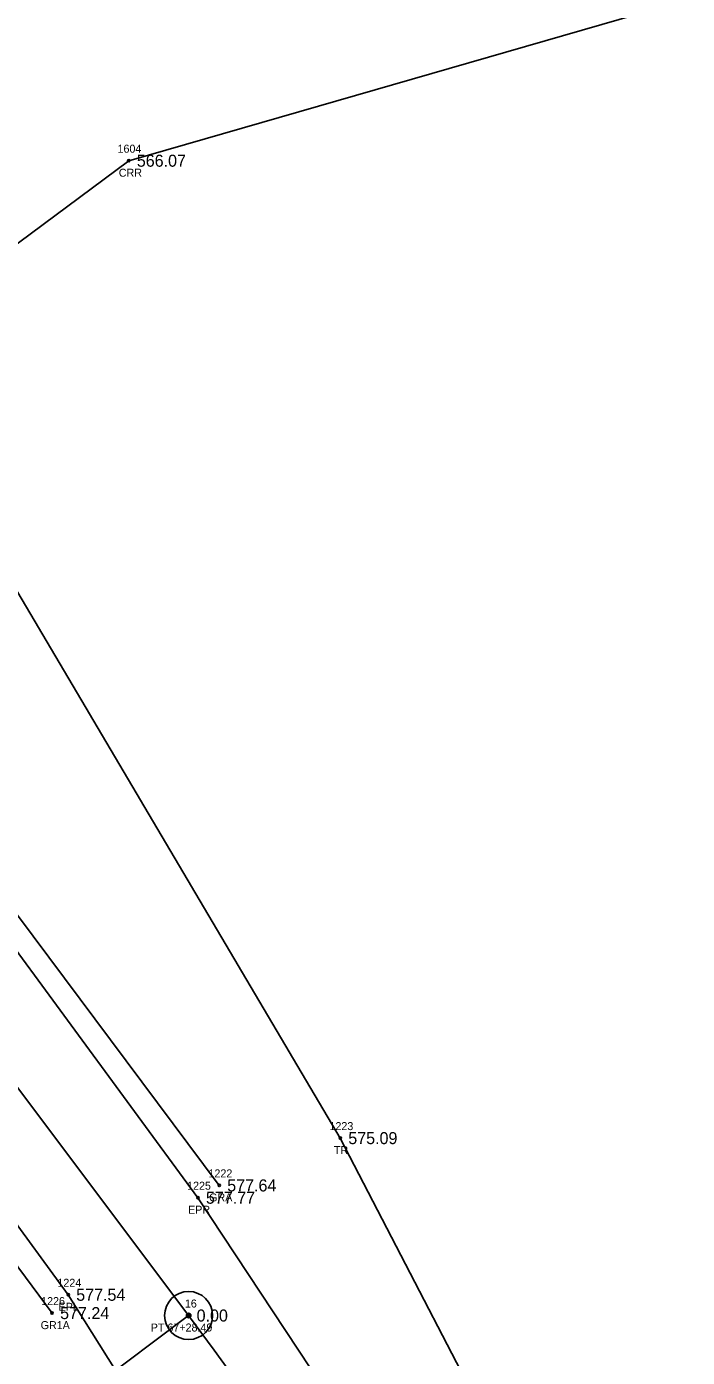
# Model space of a CAD drawing. Extents: x 1694813 to 1696862, y 1086485 to 1091027.
# Drawn here: x 1695951.1 to 1696033.6, y 1088933.9 to 1089100.2 of the extents above; entities that cross this region are included whole.
import ezdxf

# ---------------------------------------------------------------- set-up
doc = ezdxf.new("R2010")
doc.units = 0
for name, color, linetype in [('RD_EX_GuardRail', 7, 'Continuous'), ('RD_EX_GuardRail_txCode', 7, 'Continuous'), ('RD_EX_H2O', 7, 'Continuous'), ('RD_EX_H2O_txCode', 7, 'Continuous'), ('RD_EX_Road', 7, 'Continuous'), ('RD_EX_Road_txCode', 7, 'Continuous'), ('RD_EX_TX_GuardRail_ELEV', 7, 'Continuous'), ('RD_EX_TX_H2O_ELEV', 7, 'Continuous'), ('RD_EX_TX_Road_ELEV', 7, 'Continuous'), ('RD_EX_TX_VEG_ELEV', 7, 'Continuous'), ('RD_EX_VEG', 7, 'Continuous'), ('RD_EX_VEG_txCode', 7, 'Continuous'), ('RD_HC_Cl', 7, 'Continuous'), ('RD_HC_Data', 7, 'Continuous'), ('RD_HC_Survey_ELEV', 7, 'Continuous'), ('RD_HC_txCode', 7, 'Continuous'), ('RD_SMD_Locator', 7, 'Continuous')]:
    doc.layers.add(name, color=color, linetype=linetype)

msp = doc.modelspace()

# ---------------------------------------------------------------- linework, layer by layer
at = {"layer": 'RD_EX_GuardRail'}
for points in [[(1695954.25, 1088939.4), (1695922.07, 1088982.8), (1695888.95, 1089026.55), (1695824.62, 1089111.72), (1695774.33, 1089183.16), (1695747.02, 1089230.32), (1695728.79, 1089274.77), (1695712.04, 1089332.59)], [(1695975.12, 1088955.36), (1695942.2, 1088999.47), (1695910.75, 1089040.94), (1695844.49, 1089129.18), (1695795.31, 1089197.37)]]:
    msp.add_lwpolyline(points, dxfattribs=at)
at = {"layer": 'RD_EX_H2O'}
msp.add_lwpolyline([(1695520.92, 1088704.05), (1695627.53, 1088770.84), (1695697.51, 1088817.15), (1695757.08, 1088884.85), (1695828.4, 1088961.5), (1695887.69, 1089025.09), (1695910.13, 1089043.49), (1695963.83, 1089083.42), (1696041.69, 1089105.91), (1696137.07, 1089082.48), (1696174.24, 1089034.61), (1696185.76, 1089011.54), (1696200.45, 1088973.14), (1696214.06, 1088899.28)], dxfattribs=at)
at = {"layer": 'RD_EX_Road'}
for points in [[(1695879.87, 1087561.29), (1695893.33, 1087665.71), (1695905.96, 1087767.16), (1695918.66, 1087869.54), (1695930.87, 1087972.82), (1695936.26, 1088023.68), (1695942.14, 1088076.32), (1695948.07, 1088128.17), (1695955.04, 1088181.4), (1695962.88, 1088230.72), (1695971.68, 1088284.64), (1695982.02, 1088336.12), (1695993.28, 1088388.48), (1696018.75, 1088494.48), (1696045.23, 1088599.95), (1696055.72, 1088654.41), (1696060.15, 1088705.35), (1696055.83, 1088758.02), (1696044.01, 1088812.16), (1696026.4, 1088860.33), (1696000.41, 1088911.48), (1695972.46, 1088953.82), (1695939.48, 1088998.73), (1695931.21, 1088992.88)], [(1696024.81, 1088603.86), (1696034.83, 1088656.78), (1696038.52, 1088705.77), (1696034.91, 1088754.94), (1696023.53, 1088806.4), (1696006.7, 1088851.13), (1695981.74, 1088901.12), (1695956.26, 1088941.69), (1695923.39, 1088986.66), (1695931.21, 1088992.88)]]:
    msp.add_lwpolyline(points, dxfattribs=at)
at = {"layer": 'RD_EX_VEG'}
msp.add_lwpolyline([(1695933.86, 1087837.25), (1695947.67, 1087971.41), (1695951.18, 1088015.29), (1695955.07, 1088071.66), (1695974.95, 1088229.99), (1695984.06, 1088281.51), (1695991.57, 1088334), (1696002.15, 1088386.49), (1696032.05, 1088491.59), (1696059.12, 1088595.39), (1696074.06, 1088653.09), (1696077.62, 1088703.57), (1696070.4, 1088760.42), (1696059.88, 1088817.29), (1696044.37, 1088867.3), (1696013.5, 1088916.36), (1695990.24, 1088961.27), (1695859.14, 1089183.28), (1695912, 1089200.8)], dxfattribs=at)
at = {"layer": 'RD_HC_Cl'}
msp.add_line((1695971.3, 1088939.1), (1695801.51, 1089165.33), dxfattribs=at)
msp.add_arc((1695663.07, 1088707.76), 385.39, 346.4118, 36.8901, dxfattribs=at)
at = {"layer": 'RD_HC_Data'}
msp.add_line((1695971.3, 1088939.1), (1695878.76, 1088869.64), dxfattribs=at)
for radius in [3, 0.282]:
    msp.add_circle((1695971.3, 1088939.1), radius, dxfattribs=at)
at = {"layer": 'RD_SMD_Locator'}
for centre in [(1695963.83, 1089083.42), (1695990.24, 1088961.27), (1695975.12, 1088955.36), (1695972.46, 1088953.82), (1695956.26, 1088941.69), (1695954.25, 1088939.4), (1695971.3, 1088939.1)]:
    msp.add_circle(centre, 0.15, dxfattribs=at)

# ---------------------------------------------------------------- texts
at = {"layer": 'RD_EX_GuardRail_txCode'}
for s, p in [('1222', (1695973.78, 1088956.36)), ('GRA', (1695973.86, 1088953.36)), ('1226', (1695952.88, 1088940.4)), ('GR1A', (1695952.82, 1088937.4))]:
    msp.add_text(s, height=1, dxfattribs=at).set_placement(p)
at = {"layer": 'RD_EX_H2O_txCode'}
for s, p in [('1604', (1695962.42, 1089084.42)), ('CRR', (1695962.58, 1089081.42))]:
    msp.add_text(s, height=1, dxfattribs=at).set_placement(p)
at = {"layer": 'RD_EX_Road_txCode'}
for s, p in [('1225', (1695971.11, 1088954.82)), ('EPR', (1695971.23, 1088951.82)), ('1224', (1695954.91, 1088942.69)), ('EPL', (1695955.06, 1088939.69))]:
    msp.add_text(s, height=1, dxfattribs=at).set_placement(p)
at = {"layer": 'RD_EX_TX_GuardRail_ELEV'}
for s, p in [('577.64', (1695976.12, 1088954.61)), ('577.24', (1695955.25, 1088938.65))]:
    msp.add_text(s, height=1.5, dxfattribs=at).set_placement(p)
at = {"layer": 'RD_EX_TX_H2O_ELEV'}
msp.add_text('566.07', height=1.5, dxfattribs=at).set_placement((1695964.83, 1089082.67))
at = {"layer": 'RD_EX_TX_Road_ELEV'}
for s, p in [('577.77', (1695973.46, 1088953.07)), ('577.54', (1695957.26, 1088940.94))]:
    msp.add_text(s, height=1.5, dxfattribs=at).set_placement(p)
at = {"layer": 'RD_EX_TX_VEG_ELEV'}
msp.add_text('575.09', height=1.5, dxfattribs=at).set_placement((1695991.24, 1088960.52))
at = {"layer": 'RD_EX_VEG_txCode'}
for s, p in [('1223', (1695988.89, 1088962.27)), ('TR', (1695989.44, 1088959.27))]:
    msp.add_text(s, height=1, dxfattribs=at).set_placement(p)
at = {"layer": 'RD_HC_Survey_ELEV'}
msp.add_text('0.00', height=1.5, dxfattribs=at).set_placement((1695972.3, 1088938.35))
at = {"layer": 'RD_HC_txCode'}
for s, p in [('16', (1695970.83, 1088940.1)), ('PT 67+28.49', (1695966.57, 1088937.1))]:
    msp.add_text(s, height=1, dxfattribs=at).set_placement(p)

doc.saveas('drawing.dxf')
